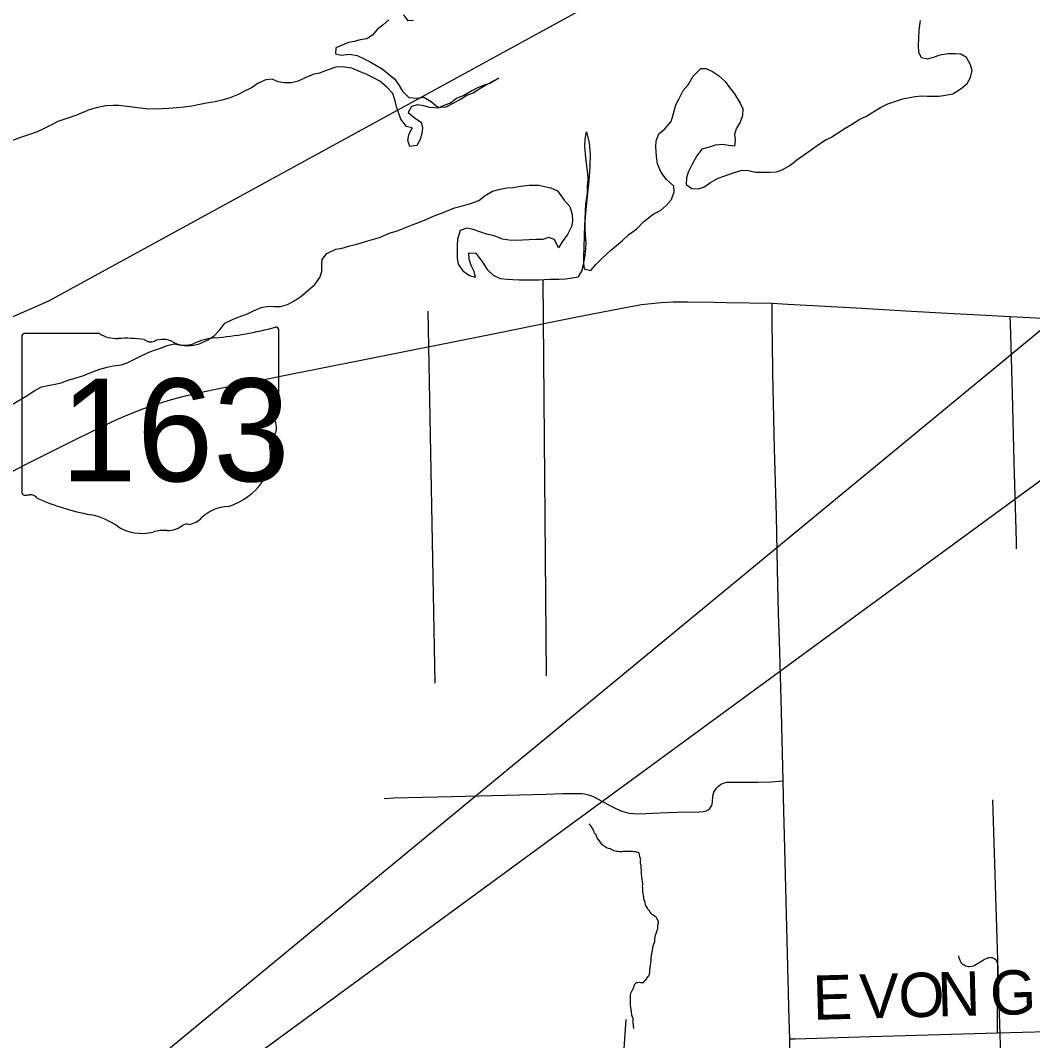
# Model space of a CAD drawing. Extents: x 0 to 34, y 0 to 22.
# Drawn here: x 6.003 to 6.652, y 18.509 to 19.163 of the extents above; entities that cross this region are included whole.
import ezdxf

# ---------------------------------------------------------------- set-up
doc = ezdxf.new("R2010")
doc.units = 0
for name, color, linetype in [('GM_X_Corporation', 7, 'Continuous'), ('GM_X_Minor_River', 7, 'Continuous'), ('GM_X_State_Location', 7, 'Continuous'), ('GM_X_State_Route', 7, 'Continuous'), ('GM_X_State_Shield', 7, 'Continuous'), ('GM_X_Township_Road', 7, 'Continuous'), ('GM_X_Township_Road_Text', 7, 'Continuous'), ('SH_Text', 7, 'Continuous')]:
    doc.layers.add(name, color=color, linetype=linetype)

msp = doc.modelspace()

# ---------------------------------------------------------------- linework, layer by layer
at = {"layer": 'GM_X_Corporation'}
msp.add_lwpolyline([(5.98911, 18.96916), (6.02093, 18.98289), (6.47248, 19.23007)], dxfattribs=at)
at = {"layer": 'GM_X_Minor_River'}
for points in [[(6.23905, 19.16312), (6.23546, 19.16006), (6.23167, 19.157), (6.22866, 19.15338), (6.22487, 19.15108), (6.2207, 19.1503), (6.21691, 19.14933), (6.2133, 19.14855), (6.20914, 19.14701), (6.20516, 19.14528), (6.2048, 19.14129), (6.2086, 19.14055), (6.21391, 19.14114), (6.21885, 19.14041), (6.22323, 19.13815), (6.22703, 19.13626), (6.23084, 19.134), (6.23484, 19.13174), (6.23922, 19.12815), (6.24285, 19.12512), (6.24572, 19.12115), (6.24782, 19.11736), (6.25183, 19.11338), (6.25734, 19.11303), (6.26151, 19.11362), (6.26627, 19.11079), (6.27047, 19.1072), (6.27211, 19.10726)], [(6.23905, 19.16312), (6.23546, 19.16006), (6.23167, 19.157), (6.22866, 19.15338), (6.22487, 19.15108), (6.2207, 19.1503), (6.21691, 19.14933), (6.2133, 19.14855), (6.20914, 19.14701), (6.20516, 19.14528), (6.2048, 19.14129), (6.2086, 19.14055), (6.21391, 19.14114), (6.21885, 19.14041), (6.22323, 19.13815), (6.22703, 19.13626), (6.23084, 19.134), (6.23484, 19.13174), (6.23922, 19.12815), (6.24285, 19.12512), (6.24572, 19.12115), (6.24782, 19.11736), (6.25183, 19.11338), (6.25734, 19.11303), (6.26151, 19.11362), (6.26627, 19.11079), (6.27047, 19.1072), (6.27578, 19.10741)], [(6.25499, 19.16281), (6.25139, 19.16261), (6.24871, 19.1664)], [(6.25499, 19.16281), (6.25139, 19.16261), (6.24871, 19.1664)], [(6.48765, 19.06565), (6.49144, 19.067), (6.49618, 19.06968), (6.50071, 19.0735), (6.50506, 19.07638), (6.50922, 19.07944), (6.51376, 19.08269), (6.51906, 19.08632), (6.52266, 19.08767), (6.53174, 19.0938), (6.5359, 19.0961), (6.5412, 19.09954), (6.54537, 19.10146), (6.54953, 19.10396), (6.55445, 19.10702), (6.55919, 19.10932), (6.56885, 19.1126), (6.57302, 19.11338), (6.57663, 19.11397), (6.5808, 19.11437), (6.58441, 19.11419), (6.592, 19.11423), (6.59618, 19.11482), (6.60073, 19.11579), (6.60621, 19.11924), (6.60999, 19.1223), (6.61225, 19.12611), (6.61318, 19.13068), (6.61221, 19.13428), (6.60953, 19.13902), (6.60591, 19.1411), (6.6023, 19.14127), (6.59775, 19.14144), (6.59244, 19.14046), (6.58827, 19.13892), (6.58429, 19.13795), (6.58068, 19.13889), (6.57895, 19.14249), (6.57874, 19.14667), (6.57909, 19.15123), (6.57926, 19.15675), (6.58017, 19.16283)], [(6.27211, 19.10726), (6.27047, 19.10663), (6.26534, 19.10698), (6.26154, 19.10811), (6.25755, 19.10866), (6.25357, 19.10769), (6.2515, 19.10369), (6.25627, 19.09991), (6.25988, 19.09745), (6.26066, 19.09385), (6.2603, 19.09023), (6.25918, 19.08643), (6.25711, 19.08262), (6.25256, 19.08203), (6.25121, 19.08582), (6.25195, 19.08943), (6.25402, 19.09382), (6.25041, 19.09475), (6.24677, 19.09948), (6.24427, 19.1067), (6.24311, 19.11125), (6.24157, 19.11599), (6.23756, 19.12016), (6.23336, 19.12375), (6.22918, 19.12601), (6.22461, 19.12827), (6.22023, 19.13015), (6.21529, 19.13222), (6.2094, 19.13314), (6.20503, 19.13274), (6.19954, 19.13081), (6.19461, 19.12908), (6.19101, 19.1283), (6.18551, 19.12599), (6.18097, 19.12388), (6.17661, 19.12272), (6.17186, 19.1227), (6.16806, 19.12344), (6.16426, 19.12513), (6.16008, 19.12473), (6.15516, 19.12262), (6.151, 19.11956), (6.14607, 19.11726), (6.1421, 19.11515), (6.1366, 19.11303), (6.13186, 19.11168), (6.12769, 19.11052), (6.12219, 19.10973), (6.11688, 19.10857), (6.11271, 19.10779), (6.10778, 19.10719), (6.10322, 19.10679), (6.09772, 19.10639), (6.09355, 19.10618), (6.08994, 19.10597), (6.0831, 19.10613), (6.07817, 19.10667), (6.07285, 19.10741), (6.06582, 19.10814), (6.06221, 19.10831), (6.05766, 19.1081), (6.0514, 19.10674), (6.04685, 19.10539), (6.03833, 19.10192), (6.03188, 19.09961), (6.02677, 19.09788), (6.02317, 19.09615), (6.01768, 19.09327), (6.01351, 19.09136), (6.00802, 19.08943), (6.0029, 19.08769), (5.99778, 19.08577)], [(6.27578, 19.10741), (6.28165, 19.11048), (6.28543, 19.11259), (6.28903, 19.11489), (6.2932, 19.11643), (6.29812, 19.11949), (6.30209, 19.12198), (6.30569, 19.1239), (6.30966, 19.12582), (6.3038, 19.12237), (6.3002, 19.12121), (6.29603, 19.11967), (6.29224, 19.11775), (6.28713, 19.11469), (6.2824, 19.11277), (6.27861, 19.10971), (6.27445, 19.10817), (6.27047, 19.10663), (6.26534, 19.10698), (6.26154, 19.10811), (6.25755, 19.10866), (6.25357, 19.10769), (6.2515, 19.10369), (6.25627, 19.09991), (6.25988, 19.09745), (6.26066, 19.09385), (6.2603, 19.09023), (6.25918, 19.08643), (6.25711, 19.08262), (6.25256, 19.08203), (6.25121, 19.08582), (6.25195, 19.08943), (6.25402, 19.09382), (6.25041, 19.09475), (6.24677, 19.09948), (6.24427, 19.1067), (6.24311, 19.11125), (6.24157, 19.11599), (6.23756, 19.12016), (6.23336, 19.12375), (6.22918, 19.12601), (6.22461, 19.12827), (6.22023, 19.13015), (6.21529, 19.13222), (6.2094, 19.13314), (6.20503, 19.13274), (6.19954, 19.13081), (6.19461, 19.12908), (6.19101, 19.1283), (6.18551, 19.12599), (6.18097, 19.12388), (6.17661, 19.12272), (6.17186, 19.1227), (6.16806, 19.12344), (6.16426, 19.12513), (6.16008, 19.12473), (6.15516, 19.12262), (6.151, 19.11956), (6.14607, 19.11726), (6.1421, 19.11515), (6.1366, 19.11303), (6.13186, 19.11168), (6.12769, 19.11052), (6.12219, 19.10973), (6.11688, 19.10857), (6.11271, 19.10779), (6.10778, 19.10719), (6.10322, 19.10679), (6.09772, 19.10639), (6.09355, 19.10618), (6.08994, 19.10597), (6.0831, 19.10613), (6.07817, 19.10667), (6.07285, 19.10741), (6.06582, 19.10814), (6.06221, 19.10831), (6.05766, 19.1081), (6.0514, 19.10674), (6.04685, 19.10539), (6.03833, 19.10192), (6.03188, 19.09961), (6.02677, 19.09788), (6.02317, 19.09615), (6.01768, 19.09327), (6.01351, 19.09136), (6.00802, 19.08943), (6.0029, 19.08769), (5.99778, 19.08577)], [(6.36307, 19.00234), (6.36418, 19.00748), (6.36492, 19.01204), (6.36546, 19.01642), (6.36563, 19.02022), (6.36523, 19.02497), (6.36501, 19.03086), (6.36499, 19.03561), (6.36515, 19.04036), (6.36551, 19.04512), (6.36606, 19.04873), (6.36642, 19.05253), (6.36659, 19.05634), (6.36695, 19.06109), (6.36674, 19.0647), (6.36595, 19.07097), (6.36536, 19.07477), (6.36475, 19.08198), (6.36492, 19.08655), (6.36584, 19.0913), (6.36759, 19.08428), (6.36819, 19.07687), (6.36804, 19.06908), (6.36733, 19.05995), (6.36624, 19.05025), (6.36534, 19.04131), (6.36463, 19.032), (6.36428, 19.02458), (6.36413, 19.01736), (6.36397, 19.01109), (6.36399, 19.0071), (6.36439, 19.00349), (6.36857, 19.00237), (6.37178, 19.00618), (6.37575, 19.01019), (6.38104, 19.01497), (6.3852, 19.01841), (6.38879, 19.02147), (6.39294, 19.02548), (6.39824, 19.02912), (6.40239, 19.0337), (6.40863, 19.03848), (6.41337, 19.04097), (6.41714, 19.04441), (6.42035, 19.04804), (6.42204, 19.05279), (6.42183, 19.0566), (6.41725, 19.06076), (6.41381, 19.0653), (6.41151, 19.0708), (6.41072, 19.07555), (6.41031, 19.08182), (6.41048, 19.08562), (6.41236, 19.09), (6.41614, 19.09325), (6.4201, 19.09802), (6.42141, 19.10221), (6.42308, 19.10868), (6.42515, 19.1123), (6.42778, 19.11782), (6.43099, 19.12145), (6.43438, 19.12698), (6.4391, 19.13194), (6.44271, 19.13196), (6.4467, 19.13008), (6.45051, 19.12743), (6.45471, 19.12365), (6.45757, 19.11968), (6.46082, 19.1157), (6.46446, 19.10983), (6.46619, 19.10603), (6.46583, 19.10185), (6.46452, 19.09747), (6.46189, 19.09328), (6.46077, 19.08966), (6.46116, 19.08605), (6.4608, 19.08225), (6.457, 19.08261), (6.4532, 19.08316), (6.44846, 19.08276), (6.44391, 19.08141), (6.43993, 19.08025), (6.43673, 19.07586), (6.43372, 19.07072), (6.43108, 19.06557), (6.42997, 19.06177), (6.4298, 19.05758), (6.43342, 19.05494), (6.43722, 19.05477), (6.44119, 19.05593), (6.44536, 19.0588), (6.45028, 19.06167), (6.45388, 19.06302), (6.45824, 19.06437), (6.46203, 19.06572), (6.46563, 19.06688), (6.46961, 19.06651), (6.47418, 19.06559), (6.47911, 19.06542), (6.48348, 19.06544), (6.48765, 19.06565)], [(6.36403, 19.00677), (6.36439, 19.00349), (6.36857, 19.00237), (6.37178, 19.00618), (6.37575, 19.01019), (6.38104, 19.01497), (6.3852, 19.01841), (6.38879, 19.02147), (6.39294, 19.02548), (6.39824, 19.02912), (6.40239, 19.0337), (6.40863, 19.03848), (6.41337, 19.04097), (6.41714, 19.04441), (6.42035, 19.04804), (6.42204, 19.05279), (6.42183, 19.0566), (6.41725, 19.06076), (6.41381, 19.0653), (6.41151, 19.0708), (6.41072, 19.07555), (6.41031, 19.08182), (6.41048, 19.08562), (6.41236, 19.09), (6.41614, 19.09325), (6.4201, 19.09802), (6.42141, 19.10221), (6.42308, 19.10868), (6.42515, 19.1123), (6.42778, 19.11782), (6.43099, 19.12145), (6.43438, 19.12698), (6.4391, 19.13194), (6.44271, 19.13196), (6.4467, 19.13008), (6.45051, 19.12743), (6.45471, 19.12365), (6.45757, 19.11968), (6.46082, 19.1157), (6.46446, 19.10983), (6.46619, 19.10603), (6.46583, 19.10185), (6.46452, 19.09747), (6.46189, 19.09328), (6.46077, 19.08966), (6.46116, 19.08605), (6.4608, 19.08225), (6.457, 19.08261), (6.4532, 19.08316), (6.44846, 19.08276), (6.44391, 19.08141), (6.43993, 19.08025), (6.43673, 19.07586), (6.43372, 19.07072), (6.43108, 19.06557), (6.42997, 19.06177), (6.4298, 19.05758), (6.43342, 19.05494), (6.43722, 19.05477), (6.44119, 19.05593), (6.44536, 19.0588), (6.45028, 19.06167), (6.45388, 19.06302), (6.45824, 19.06437), (6.46203, 19.06572), (6.46563, 19.06688), (6.46961, 19.06651), (6.47418, 19.06559), (6.47911, 19.06542), (6.48348, 19.06544), (6.48765, 19.06565)], [(6.11766, 18.95538), (6.12297, 18.95807), (6.12694, 18.96056), (6.13072, 18.96438), (6.13392, 18.96857), (6.13847, 18.97088), (6.14245, 18.97241), (6.14851, 18.97472), (6.15229, 18.97664), (6.15722, 18.97876), (6.16177, 18.97954), (6.16538, 18.97936), (6.16955, 18.97938), (6.17411, 18.98055), (6.17884, 18.98323), (6.18262, 18.98572), (6.18697, 18.98935), (6.1917, 18.99336), (6.1949, 18.99794), (6.19602, 19.00175), (6.19619, 19.00593), (6.19636, 19.00954), (6.19938, 19.01335), (6.20506, 19.01604), (6.20904, 19.01682), (6.21416, 19.01818), (6.21795, 19.01914), (6.22421, 19.02107), (6.23311, 19.02359), (6.23993, 19.02666), (6.2441, 19.02763), (6.24941, 19.02974), (6.25358, 19.03147), (6.26078, 19.03436), (6.26778, 19.03724), (6.27498, 19.04013), (6.28123, 19.04263), (6.28635, 19.04398), (6.2909, 19.04514), (6.29678, 19.04726), (6.30094, 19.05051), (6.30567, 19.05339), (6.31041, 19.05455), (6.31477, 19.05552), (6.31875, 19.05573), (6.3235, 19.05651), (6.329, 19.05711), (6.33526, 19.05714), (6.33888, 19.0562), (6.34305, 19.05546), (6.34724, 19.05358), (6.35145, 19.04752), (6.35507, 19.04355), (6.35662, 19.03842), (6.35683, 19.03481), (6.35647, 19.03101), (6.35365, 19.02548), (6.35026, 19.02072), (6.34781, 19.0169), (6.34531, 19.0224), (6.34151, 19.02353), (6.33791, 19.02237), (6.33335, 19.02235), (6.32899, 19.02214), (6.32481, 19.02193), (6.32045, 19.02172), (6.31627, 19.02189), (6.31209, 19.02263), (6.30657, 19.02469), (6.30182, 19.02581), (6.29802, 19.02693), (6.29327, 19.02862), (6.28908, 19.02955), (6.28473, 19.02801), (6.28305, 19.02249), (6.28288, 19.0185), (6.28292, 19.01014), (6.28351, 19.00653), (6.28657, 19.00217), (6.29076, 18.99915), (6.29475, 18.99822), (6.29378, 19.00182), (6.29186, 19.00562), (6.2907, 19.0096), (6.29049, 19.01378), (6.29486, 19.01361), (6.29907, 19.00774), (6.30213, 19.003), (6.30594, 18.99941), (6.31051, 18.99734), (6.31507, 18.99698), (6.31868, 18.99662), (6.32266, 18.99645), (6.33519, 18.99651), (6.3388, 18.99672), (6.34259, 18.99692), (6.3481, 18.99695), (6.35246, 18.99716), (6.35683, 18.99775), (6.36081, 18.99834), (6.36307, 19.00234)], [(6.36307, 19.00234), (6.36403, 19.00677)], [(6.33777, 18.99666), (6.3399, 18.74243)], [(6.26411, 18.97641), (6.26855, 18.73772)], [(5.99769, 18.91681), (6.0064, 18.92179), (6.01208, 18.92543), (6.01624, 18.92773), (6.02041, 18.9287), (6.02402, 18.92929), (6.02895, 18.93045), (6.03349, 18.93218), (6.03861, 18.93354), (6.04278, 18.93489), (6.0479, 18.937), (6.05377, 18.93912), (6.05832, 18.94047), (6.0623, 18.94125), (6.06761, 18.94204), (6.07122, 18.94319), (6.08068, 18.94799), (6.0858, 18.95029), (6.0894, 18.95164), (6.09319, 18.9528), (6.09698, 18.95434), (6.10134, 18.95531), (6.10571, 18.95457), (6.10989, 18.95421), (6.11368, 18.95461), (6.11766, 18.95538)], [(6.62619, 18.663), (6.63139, 18.49883), (6.60918, 18.49815), (6.60813, 18.36834)], [(6.38175, 18.63112), (6.38137, 18.6315), (6.38005, 18.6319), (6.3793, 18.6321), (6.37854, 18.63249), (6.37779, 18.63288), (6.37666, 18.63366), (6.3761, 18.63423), (6.37536, 18.63519), (6.37425, 18.63673), (6.37331, 18.63788), (6.37276, 18.63865), (6.37258, 18.63922), (6.3722, 18.63961), (6.37202, 18.63999), (6.37203, 18.64056), (6.37147, 18.64114), (6.3711, 18.64171), (6.37073, 18.64248), (6.37036, 18.64343), (6.37018, 18.644), (6.36962, 18.64458), (6.36944, 18.64515), (6.36907, 18.64573), (6.36851, 18.6465), (6.36814, 18.64707), (6.36758, 18.64765)], [(6.39617, 18.51641), (6.39585, 18.52021), (6.3957, 18.52287), (6.39515, 18.52421), (6.39497, 18.52497), (6.39481, 18.52706), (6.39412, 18.53144), (6.39416, 18.53429), (6.39398, 18.53486), (6.39402, 18.53771), (6.39423, 18.53903), (6.39521, 18.54073), (6.39618, 18.54261), (6.39659, 18.54451), (6.39793, 18.54582), (6.39869, 18.54581), (6.39983, 18.54598), (6.4004, 18.54597), (6.40116, 18.54577), (6.40211, 18.54576), (6.40268, 18.54594), (6.40288, 18.5467), (6.40384, 18.54763), (6.40539, 18.5497), (6.40616, 18.55045), (6.40636, 18.55158), (6.40656, 18.55234), (6.40658, 18.55367), (6.40701, 18.55708), (6.40724, 18.55974), (6.40726, 18.56126), (6.40749, 18.56372), (6.40768, 18.5641), (6.40769, 18.56429), (6.40789, 18.56542), (6.40871, 18.5694), (6.4097, 18.57223), (6.40971, 18.5728), (6.40994, 18.57565), (6.41093, 18.57848), (6.41133, 18.58), (6.41152, 18.58037), (6.41155, 18.58189), (6.41156, 18.58284), (6.41196, 18.58417), (6.41197, 18.58473), (6.41161, 18.58607), (6.41105, 18.58684), (6.4105, 18.58779), (6.40918, 18.58857), (6.40824, 18.58934), (6.40768, 18.58973), (6.40731, 18.59012), (6.40694, 18.59069), (6.40638, 18.59127), (6.4062, 18.59184), (6.40507, 18.593), (6.4049, 18.59376), (6.40397, 18.5951), (6.4036, 18.59587), (6.40343, 18.5972), (6.40271, 18.59949), (6.40254, 18.60082), (6.40235, 18.60101), (6.40236, 18.60158), (6.40219, 18.60291), (6.40202, 18.60443), (6.40205, 18.60652), (6.40187, 18.60729), (6.40189, 18.60842), (6.4019, 18.60937), (6.40173, 18.61052), (6.40157, 18.61223), (6.40123, 18.61527), (6.40106, 18.6166), (6.40108, 18.61793), (6.40091, 18.61888), (6.40093, 18.62059), (6.40058, 18.62268), (6.4006, 18.62363), (6.40041, 18.62402), (6.40061, 18.62458), (6.40025, 18.62573), (6.3999, 18.62763), (6.39972, 18.62877), (6.39897, 18.62916), (6.39803, 18.62937), (6.39746, 18.62956), (6.39613, 18.62958), (6.39538, 18.62978), (6.39102, 18.62985), (6.39026, 18.62986), (6.3895, 18.62987), (6.38855, 18.62969), (6.38704, 18.62971), (6.38628, 18.62991), (6.38533, 18.62993), (6.38344, 18.63033), (6.38288, 18.63053), (6.38269, 18.63072), (6.38175, 18.63112)], [(6.39114, 18.52221), (6.38884, 18.4878), (6.37386, 18.48564), (6.37865, 18.28897), (6.35079, 18.28066), (6.35168, 18.21681)]]:
    msp.add_lwpolyline(points, dxfattribs=at)
at = {"layer": 'GM_X_State_Route'}
msp.add_line((6.63768, 18.97294), (6.69764, 18.96994), dxfattribs=at)
for points in [[(6.34818, 18.97037), (6.36307, 18.97327), (6.38746, 18.97808), (6.40124, 18.98054), (6.40741, 18.98137), (6.41362, 18.98192), (6.4214, 18.98227), (6.43074, 18.98235), (6.44748, 18.98208)], [(6.44748, 18.98208), (6.4556, 18.98195), (6.48491, 18.98139)], [(6.48491, 18.98139), (6.49508, 18.98087), (6.53882, 18.97847), (6.57422, 18.97637), (6.59733, 18.97511)], [(6.4999, 18.34733), (6.4983, 18.4182), (6.49782, 18.44148), (6.49709, 18.47253), (6.4963, 18.50512), (6.4962, 18.50974), (6.49592, 18.5222), (6.49285, 18.64016), (6.4924, 18.65568), (6.49195, 18.67513), (6.49092, 18.71933), (6.48978, 18.75808), (6.48902, 18.78272), (6.48838, 18.8108), (6.48776, 18.84505), (6.48647, 18.88829), (6.48542, 18.93662), (6.48511, 18.95681), (6.48493, 18.96654), (6.48491, 18.98139)], [(6.59733, 18.97511), (6.62194, 18.97377), (6.63768, 18.97294)], [(5.912, 18.82597), (5.91232, 18.82621), (5.91873, 18.83062), (5.92661, 18.83564), (5.93464, 18.84039), (5.94555, 18.84637), (5.9744, 18.86162), (6.00612, 18.87806), (6.03389, 18.89201), (6.05203, 18.9009), (6.06469, 18.90685), (6.07327, 18.91054), (6.08196, 18.91393), (6.09078, 18.91701), (6.0997, 18.91976), (6.10872, 18.92217), (6.12086, 18.92492), (6.14047, 18.92892), (6.15915, 18.93264), (6.17822, 18.93636), (6.2214, 18.94501), (6.31127, 18.96298), (6.34173, 18.96911), (6.34818, 18.97037)]]:
    msp.add_lwpolyline(points, dxfattribs=at)
at = {"layer": 'GM_X_State_Shield'}
for p, q in [((6.00367, 18.96025), (6.00367, 18.86019)), ((6.05356, 18.96197), (6.0053, 18.96197)), ((6.16847, 18.91211), (6.16847, 18.96445)), ((6.16845, 18.91212), (6.16847, 18.91211))]:
    msp.add_line(p, q, dxfattribs=at)
for centre, major_axis, start_param, end_param in [((6.10976, 19.09838), (0.17476, 0), 4.814394, 5.042369), ((6.16664, 18.96467), (0.00183, 0), 6.141152, 7.989035), ((6.00556, 18.96046), (0.00191, 0), 1.712693, 3.28349), ((6.06505, 18.97358), (0.01852, 0), 4.042523, 4.731795), ((6.07119, 18.90579), (0.06648, 0), 1.404758, 1.657858), ((6.09412, 18.94941), (0.01111, 0), 0.950623, 2.079405), ((6.13206, 18.93141), (0.03516, 0), 1.699011, 2.107814), ((6.08628, 18.96098), (0.00534, 0), 3.836095, 5.185415), ((6.10846, 18.96528), (0.01336, 0), 4.081561, 5.145723), ((6.16804, 18.90826), (0.00284, 0), 1.883978, 3.671073), ((6.14998, 18.90165), (0.01704, 0), 5.934695, 6.695948), ((6.16651, 18.9119), (0.00196, 0), 5.05454, 6.418171), ((6.17504, 18.8902), (0.0124, 0), 2.387724, 3.262537), ((6.11955, 18.88354), (0.04371, 0), 5.101752, 6.440018), ((6.00558, 18.85997), (0.00193, 0), 3.00124, 4.508301), ((6.00587, 18.8702), (0.0147, 0), 4.665946, 4.897461), ((6.00888, 18.85441), (0.0053, 0), 0.519207, 1.627899), ((6.07579, 18.94431), (0.1262, 0), 4.195997, 4.488961), ((6.13799, 18.83209), (0.02394, 0), 1.647645, 2.488434), ((6.03817, 18.81523), (0.03949, 0), 0.823519, 1.323587), ((6.10765, 18.85049), (0.01412, 0), 4.937069, 5.64225), ((6.08087, 18.85392), (0.02506, 0), 4.026481, 4.996735), ((6.09535, 18.81932), (0.02059, 0), 1.495662, 1.94098), ((6.09718, 18.84642), (0.01335, 0), 4.691044, 5.507374), ((6.10926, 18.83673), (0.00376, 0), 1.147584, 2.315152)]:
    msp.add_ellipse(centre, major_axis=major_axis, ratio=0.8, start_param=start_param, end_param=end_param, dxfattribs=at)
at = {"layer": 'GM_X_Township_Road'}
for points in [[(6.64164, 18.82392), (6.64165, 18.82859), (6.64024, 18.87983), (6.63914, 18.9233), (6.63841, 18.94659), (6.63781, 18.96832), (6.63768, 18.97294)], [(6.23605, 18.66395), (6.24225, 18.66434), (6.27945, 18.66517), (6.3399, 18.66669), (6.35075, 18.66701), (6.36005, 18.66711), (6.36315, 18.667), (6.36468, 18.66681), (6.3662, 18.66651), (6.36769, 18.66608), (6.36914, 18.66554), (6.37195, 18.66423), (6.38008, 18.6597), (6.38423, 18.65759), (6.38851, 18.65578), (6.39147, 18.65486), (6.39298, 18.65454), (6.39606, 18.65417), (6.39916, 18.65413), (6.4131, 18.65474), (6.42395, 18.65508), (6.4379, 18.65533), (6.44101, 18.65552), (6.44252, 18.65586), (6.44389, 18.65653), (6.44503, 18.65755), (6.44587, 18.65883), (6.44637, 18.66029), (6.44661, 18.66184), (6.44684, 18.66494), (6.4471, 18.66646), (6.44762, 18.66791), (6.44837, 18.66927), (6.44932, 18.67049), (6.4504, 18.67162), (6.45158, 18.67261), (6.45289, 18.67344), (6.45433, 18.674), (6.45582, 18.67424), (6.45769, 18.67429), (6.47583, 18.67441), (6.48429, 18.67464), (6.48961, 18.67498), (6.49195, 18.67513)], [(6.62946, 18.51351), (6.6297, 18.5529), (6.6297, 18.55525), (6.6297, 18.55667), (6.6296, 18.55758), (6.62942, 18.55836), (6.62912, 18.55912), (6.62882, 18.55975), (6.62855, 18.56009), (6.628, 18.56063), (6.62761, 18.56095), (6.62704, 18.56133), (6.62633, 18.56162), (6.62567, 18.56172), (6.62495, 18.56181), (6.62441, 18.56177), (6.6236, 18.56163), (6.62297, 18.5614), (6.62218, 18.5611), (6.62122, 18.5606), (6.61986, 18.55983), (6.61453, 18.55663), (6.6138, 18.55627), (6.61308, 18.5561), (6.61156, 18.55588), (6.61091, 18.55588), (6.61002, 18.55603), (6.60906, 18.55639), (6.60808, 18.5569), (6.60732, 18.55744), (6.60667, 18.55808), (6.60628, 18.55859), (6.6055, 18.55993), (6.60498, 18.5614), (6.6047, 18.56292)], [(6.62946, 18.51351), (6.70975, 18.51581), (6.77634, 18.51769), (6.77704, 18.51764), (6.7776, 18.51761), (6.7783, 18.51757), (6.77876, 18.51752), (6.77918, 18.51745), (6.7797, 18.5173), (6.78012, 18.51708), (6.78073, 18.51672), (6.78102, 18.51649)], [(6.4962, 18.50974), (6.49981, 18.50984), (6.54802, 18.51117), (6.62946, 18.51351)]]:
    msp.add_lwpolyline(points, dxfattribs=at)
at = {"layer": 'SH_Text'}
msp.add_lwpolyline([(5.61399, 18.10416), (9.32697, 20.82299), (9.32697, 21.16525)], close=True, dxfattribs=at)

# ---------------------------------------------------------------- texts
at = {"layer": 'GM_X_State_Location'}
for s, p in [('s', (6.08422, 18.90356)), ('r', (6.08421, 18.90356))]:
    msp.add_text(s, height=0.0000947, dxfattribs=at).set_placement(p)
msp.add_text('163', height=0.0000947, rotation=0.00001, dxfattribs=at).set_placement((6.05079, 18.89667))
at = {"layer": 'GM_X_State_Shield'}
msp.add_text('163', height=0.065918, dxfattribs=at).set_placement((6.02841, 18.86724))
at = {"layer": 'GM_X_Township_Road_Text'}
for s, rotation, p in [('N', 1.53163, (6.59129, 18.52402)), ('G', 1.53163, (6.62504, 18.52492)), ('E', 1.53449, (6.51132, 18.52187)), ('V', 1.53163, (6.54132, 18.52268)), ('O', 1.53163, (6.56631, 18.52335))]:
    msp.add_text(s, height=0.02841, rotation=rotation, dxfattribs=at).set_placement(p)

doc.saveas('drawing.dxf')
